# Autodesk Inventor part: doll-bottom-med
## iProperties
Author: Administrator
Created: 2001-10
Part Number: doll-bottom-med
Document SubType Name: Modeling
Designer: Administrator
Control State: 0
Master: False
Checked Out: False
PropertySet Name: Design Tracking Control
Shininess: 64.0
Angle Display Precision: 2
Document Length Units: 11272
Document Angle Units: 11286
Document Time Units: 11279
Document Mass Units: 11290
Document Length Units Precision: 3
Document Angle Units Precision: 2
Compacted: True
PropertySet Name: _Private Model Information
Density: 0.0
Volumn: 0.0
Area: 0.0
PropertySet Name: Model Information
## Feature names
1. Derived Body1 [Tagging]
